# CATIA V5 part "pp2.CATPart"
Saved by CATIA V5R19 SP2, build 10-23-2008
Part number: pp2
Publications: "Line.1", "Line.2", "Line.3", "Point.3", "Point.4", "Line.4", "Line.5", "Line.6", "Line.7", "Plane.1"
Bounding box of the stored display mesh (mm): x 0 to 10, y 0 to 136, z -50 to 50
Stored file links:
  C:\Users\Welcome\Documents\thinkm2\pp2.CATPart
  C:\Users\Welcome\Documents\thinkm2\Brasmeca.CATProduct
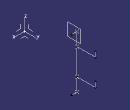
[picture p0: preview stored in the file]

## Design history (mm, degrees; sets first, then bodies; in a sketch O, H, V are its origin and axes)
AxisSystem1: origin (0, 0, 0), X (1, 0, 0), Y (0, 1, 0), Z (0, 0, 1)
Set1
  Point1: linked copy from another document
  Point2: linked copy from another document
Body1 (main body)
  Line1: type PtPt, FirstPoint Point1, SecondPoint Point2
  Line2: type PtDir, RefPoint Point1, Direction edge [XY plane of AxisSystem1 | ZX plane of AxisSystem1], Start 0, End 10
  Line3: type PtDir, RefPoint Point2, Direction edge [XY plane of AxisSystem1 | ZX plane of AxisSystem1], Start 0, End 10
  Point3: type OnCurve, Support Line1, Length 25
  Point4: type OnCurve, Support Line1, Length 75
  Line4: type PtDir, RefPoint Point3, Direction edge [YZ plane of AxisSystem1 | XY plane of AxisSystem1], Start 0, End 36
  Line5: type PtDir, RefPoint Point4, Direction edge [YZ plane of AxisSystem1 | XY plane of AxisSystem1], Start 0, End 36
  Line6: type PtDir, RefPoint vertex of Line4, Direction edge [ZX plane of AxisSystem1 | YZ plane of AxisSystem1], Start 0, End 10
  Line7: type PtDir, RefPoint vertex of Line5, Direction edge [ZX plane of AxisSystem1 | YZ plane of AxisSystem1], Start 0, End 10
  Plane1: type Normal, Curve Line2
